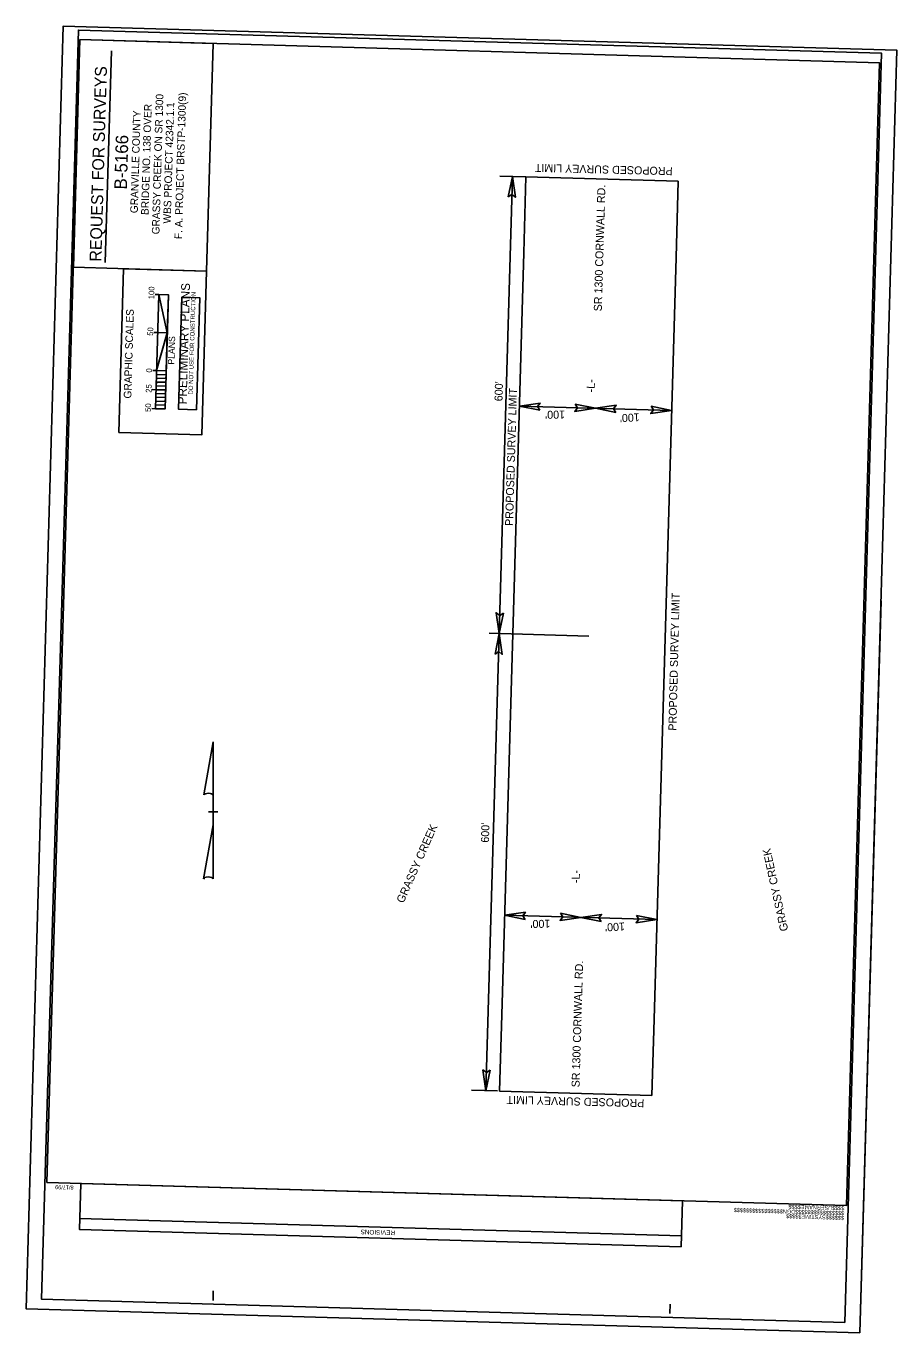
# Model space of a CAD drawing. Extents: x 2098010 to 2099153, y 990167 to 991881.
import ezdxf

# ---------------------------------------------------------------- set-up
doc = ezdxf.new("R2010")
doc.units = 0
for name, color, linetype in [('Default', 7, 'Continuous'), ('Prop Horizontal Alignment', 7, 'Continuous'), ('Prop North Arrow for Plan Sheets CELL', 7, 'Continuous'), ('Prop RDY Alternate Text Blue', 7, 'Continuous'), ('Prop Terminator CELL', 7, 'Continuous'), ('Sheet Block Revision CELL', 7, 'Continuous'), ('Sheet Cutting Line CELL', 7, 'Continuous'), ('Sheet Data Field CELL', 7, 'Continuous'), ('Sheet Plan CELL', 7, 'Continuous'), ('Sheet Plot Border Inside CELL', 7, 'Continuous'), ('Sheet Plot Border Outside CELL', 7, 'Continuous'), ('Sheet Sticker Preliminary CELL', 7, 'Continuous'), ('Sheet Title CELL', 7, 'Continuous')]:
    doc.layers.add(name, color=color, linetype=linetype)

msp = doc.modelspace()

# ---------------------------------------------------------------- linework, layer by layer
at = {"layer": 'Default'}
for p, q in [((2098114, 991571.4), (2098122, 991849)), ((2099104.6, 990167), (2099132.4, 991127.4))]:
    msp.add_line(p, q, dxfattribs=at)
at = {"layer": 'Prop Horizontal Alignment'}
for p, q in [((2098613.8, 990484.7), (2098648.5, 991684.2)), ((2098666.3, 991683.7), (2098632, 991684.6)), ((2098663.4, 991583.8), (2098666.3, 991683.7)), ((2098666.3, 991683.7), (2098866.2, 991678)), ((2098866.2, 991678), (2098863.3, 991578)), ((2098634.5, 990584.2), (2098663.4, 991583.8)), ((2098834.4, 990578.4), (2098863.3, 991578)), ((2098857.5, 991377.1), (2098657.6, 991382.9)), ((2098748.9, 991081), (2098618, 991084.8)), ((2098838.2, 990709.1), (2098638.3, 990714.9)), ((2098634.5, 990584.2), (2098631.6, 990484.2)), ((2098831.5, 990478.5), (2098834.4, 990578.4)), ((2098629.1, 990484.3), (2098594.8, 990485.2)), ((2098631.6, 990484.2), (2098831.5, 990478.5))]:
    msp.add_line(p, q, dxfattribs=at)
for points in [[(2098072.1, 991565), (2098080.7, 991863.8), (2098255.6, 991858.7), (2098246.9, 991559.9)], [(2098131.8, 991348.2), (2098138, 991563.1), (2098246.9, 991559.9), (2098240.7, 991345.1)]]:
    msp.add_lwpolyline(points, close=True, dxfattribs=at)
at = {"layer": 'Prop North Arrow for Plan Sheets CELL'}
for p, q in [((2098243.3, 990872.7), (2098255.6, 990942.2)), ((2098255.7, 990942.2), (2098255.6, 990942.2)), ((2098255.7, 990942.2), (2098255.6, 990942.2)), ((2098255.7, 990942.2), (2098255.7, 990870.5)), ((2098255.7, 990833.3), (2098255.7, 990872.6)), ((2098255.7, 990870.5), (2098255.7, 990872.6)), ((2098249.7, 990850.7), (2098249.6, 990850.7)), ((2098249.7, 990850.7), (2098261.7, 990850.7)), ((2098255, 990850.7), (2098249.7, 990850.7)), ((2098255.7, 990833.3), (2098243.1, 990762.5)), ((2098255.7, 990762.8), (2098255.7, 990833.3))]:
    msp.add_line(p, q, dxfattribs=at)
for centre, start_param, end_param in [((2098249.5, 990872), 0.216388, 2.908219), ((2098249.5, 990762.2), 0.201328, 3.141593)]:
    msp.add_ellipse(centre, major_axis=(6.34, -0.05), ratio=0.461098, start_param=start_param, end_param=end_param, dxfattribs=at)
at = {"layer": 'Prop Terminator CELL'}
for points in [[(2098643.1, 991657.3), (2098648.5, 991684.2), (2098652.5, 991656.9), (2098647.8, 991660.5)], [(2098684.5, 991377.5), (2098657.6, 991382.9), (2098684.9, 991386.9), (2098681.3, 991382.2)], [(2098730.7, 991385.5), (2098757.6, 991380), (2098730.3, 991376), (2098733.9, 991380.7)], [(2098784.4, 991374.6), (2098757.6, 991380), (2098784.8, 991384), (2098781.3, 991379.3)], [(2098830.7, 991382.6), (2098857.5, 991377.1), (2098830.2, 991373.1), (2098833.8, 991377.8)], [(2098636.6, 991111.3), (2098631.2, 991084.4), (2098627.1, 991111.7), (2098631.8, 991108.1)], [(2098625.7, 991057.6), (2098631.2, 991084.4), (2098635.2, 991057.2), (2098630.5, 991060.8)], [(2098665.1, 990709.4), (2098638.3, 990714.9), (2098665.6, 990718.9), (2098662, 990714.2)], [(2098711.4, 990717.4), (2098738.2, 990712), (2098711, 990708), (2098714.5, 990712.7)], [(2098765.1, 990706.5), (2098738.2, 990712), (2098765.5, 990716), (2098761.9, 990711.3)], [(2098811.3, 990714.5), (2098838.2, 990709.1), (2098810.9, 990705.1), (2098814.5, 990709.8)], [(2098619.2, 990511.5), (2098613.8, 990484.7), (2098609.8, 990512), (2098614.5, 990508.4)]]:
    msp.add_lwpolyline(points, close=True, dxfattribs=at)
at = {"layer": 'Sheet Block Revision CELL'}
msp.add_line((2098870.6, 990294.3), (2098080.3, 990317.1), dxfattribs=at)
msp.add_lwpolyline([(2098870.2, 990279.7), (2098079.9, 990302.6), (2098081.7, 990363.1), (2098872, 990340.3)], close=True, dxfattribs=at)
at = {"layer": 'Sheet Cutting Line CELL'}
for p, q in [((2098058.7, 991881.4), (2098010, 990198.6)), ((2099104.6, 990167), (2099153.3, 991849.7)), ((2098010, 990198.6), (2099104.6, 990167))]:
    msp.add_line(p, q, dxfattribs=at)
at = {"layer": 'Sheet Data Field CELL'}
for p, q in [((2098184.3, 991529.4), (2098179.3, 991529.5)), ((2098182.8, 991479.4), (2098177.9, 991479.6)), ((2098180.7, 991404.4), (2098175.7, 991404.6)), ((2098179.9, 991379.5), (2098175, 991379.6))]:
    msp.add_line(p, q, dxfattribs=at)
at = {"layer": 'Sheet Plan CELL'}
for p, q in [((2098037.3, 990364.4), (2098037.3, 990364.4)), ((2099086.9, 990334), (2099086.9, 990334)), ((2098255.5, 990209.5), (2098255.8, 990222)), ((2098855.2, 990192.2), (2098855.6, 990204.7))]:
    msp.add_line(p, q, dxfattribs=at)
msp.add_lwpolyline([(2098080.7, 991863.8), (2098037.3, 990364.4), (2099086.9, 990334), (2099130.3, 991833.4)], close=True, dxfattribs=at)
at = {"layer": 'Sheet Plot Border Inside CELL'}
msp.add_lwpolyline([(2099085, 990180.5), (2099133.1, 991845.8), (2098078.6, 991876.3), (2098030.4, 990211)], close=True, dxfattribs=at)
at = {"layer": 'Sheet Plot Border Outside CELL'}
msp.add_lwpolyline([(2099104.6, 990167), (2099153.3, 991849.7), (2098058.7, 991881.4), (2098010, 990198.6)], close=True, dxfattribs=at)
at = {"layer": 'Sheet Sticker Preliminary CELL'}
msp.add_lwpolyline([(2098233.7, 991378.1), (2098210.2, 991378.8), (2098214.4, 991525.7), (2098237.9, 991525.1)], close=True, dxfattribs=at)
at = {"layer": 'Sheet Title CELL'}
for p, q in [((2098184.3, 991529.4), (2098179.3, 991529.5)), ((2098184.3, 991529.4), (2098180, 991379.4)), ((2098196.8, 991529), (2098184.3, 991529.4)), ((2098192.5, 991379.1), (2098196.8, 991529)), ((2098182.8, 991479.4), (2098177.9, 991479.5)), ((2098182.8, 991479.4), (2098195.3, 991479)), ((2098181.4, 991429.4), (2098176.4, 991429.6)), ((2098180.7, 991404.4), (2098175.7, 991404.6)), ((2098181, 991414.4), (2098193.5, 991414.1)), ((2098180, 991379.4), (2098175, 991379.6)), ((2098175, 991379.6), (2098175, 991379.6)), ((2098180, 991379.4), (2098192.5, 991379.1)), ((2098180, 991379.4), (2098180, 991379.4))]:
    msp.add_line(p, q, dxfattribs=at)
for points in [[(2098184.3, 991529.4), (2098195.3, 991479), (2098196.8, 991529)], [(2098181.4, 991429.4), (2098195.3, 991479), (2098193.9, 991429.1)], [(2098181.1, 991419.4), (2098181.3, 991424.4), (2098193.8, 991424.1), (2098193.6, 991419.1)], [(2098180.5, 991399.4), (2098180.7, 991404.4), (2098193.2, 991404.1), (2098193, 991399.1)], [(2098180.8, 991409.4), (2098181, 991414.4), (2098193.5, 991414.1), (2098193.3, 991409.1)], [(2098180.2, 991389.4), (2098180.4, 991394.4), (2098192.9, 991394.1), (2098192.8, 991389.1)], [(2098180, 991379.4), (2098180.1, 991384.4), (2098192.6, 991384.1), (2098192.5, 991379.1)]]:
    msp.add_lwpolyline(points, close=True, dxfattribs=at)

# ---------------------------------------------------------------- texts
at = {"layer": 'Prop Horizontal Alignment'}
for s, height, rotation, p in [('REQUEST FOR SURVEYS', 15.624, 88.3429, (2098108.8, 991572.2)), ('GRASSY CREEK ON SR 1300', 9.96, 88.3429, (2098185, 991608.1)), ('F. A. PROJECT BRSTP-1300(9)', 9.96, 88.3429, (2098214.7, 991601.9)), ('GRANVILLE COUNTY', 9.96, 88.3429, (2098156.6, 991635.9)), ('BRIDGE NO. 138 OVER ', 9.96, 88.3429, (2098170.8, 991633.5)), ('WBS PROJECT 42342.1.1', 9.96, 88.3429, (2098199.9, 991622.3)), ('B-5166', 16.6, 88.3429, (2098142.3, 991666.9)), ('PROPOSED SURVEY LIMIT', 10.5, 178.5674, (2098859, 991696.3)), ('SR 1300 CORNWALL RD.', 10.5, 88.3429, (2098765.8, 991507.1)), ("600'", 10.5, 88.3429, (2098635.4, 991389.1)), ('PROPOSED SURVEY LIMIT', 10.5, 88.3429, (2098649.3, 991225.5)), ('-L-', 10.5, 88.3429, (2098756.4, 991400.8)), ("100'", 10.5, 180.8331, (2098717.5, 991377.1)), ("100'", 10.5, 183.075, (2098815.3, 991373.6)), ('PROPOSED SURVEY LIMIT', 10.5, 88.5946, (2098863.7, 990956.9)), ("600'", 10.5, 88.3429, (2098617.6, 990810)), ('-L-', 10.5, 88.3429, (2098736.7, 990756.9)), ("100'", 10.5, 180.8331, (2098698.2, 990709)), ("100'", 10.5, 183.075, (2098795.9, 990705.5)), ('SR 1300 CORNWALL RD.', 10.5, 88.3429, (2098736.6, 990489)), ('PROPOSED SURVEY LIMIT', 10.5, 178.5674, (2098821.8, 990473.5))]:
    msp.add_text(s, height=height, rotation=rotation, dxfattribs=at).set_placement(p)
at = {"layer": 'Prop RDY Alternate Text Blue'}
for rotation, p in [(66.1064, (2098505.4, 990729.9)), (102.3437, (2099010.7, 990695.1))]:
    msp.add_text('GRASSY CREEK', height=10.5, rotation=rotation, dxfattribs=at).set_placement(p)
at = {"layer": 'Sheet Block Revision CELL'}
msp.add_text('REVISIONS', height=6, rotation=178.3429, dxfattribs=at).set_placement((2098494.5, 990301.1))
at = {"layer": 'Sheet Data Field CELL'}
for s, p in [('100', (2098178.1, 991523)), ('50', (2098176.7, 991475.1)), ('25', (2098174.6, 991400.3)), ('50', (2098173.8, 991375.2))]:
    msp.add_text(s, height=7.5, rotation=88.3429, dxfattribs=at).set_placement(p)
at = {"layer": 'Sheet Plan CELL'}
for s, p in [('8/17/99', (2098072.4, 990360.1)), ('$$$$$$$$$$$$$$$$DGN$$$$$$$$$$$$$$$$', (2099084.3, 990326.5)), ('$$$$USERNAME$$$$', (2099084.5, 990333)), ('$$$$$$SYSTIME$$$$$', (2099084.1, 990320.4))]:
    msp.add_text(s, height=5.25, rotation=178.3429, dxfattribs=at).set_placement(p)
at = {"layer": 'Sheet Sticker Preliminary CELL'}
for s, height, p in [('PRELIMINARY PLANS', 11.52, (2098220.7, 991385)), ('DO NOT USE FOR CONSTRUCTION', 5.76, (2098228.8, 991397.9))]:
    msp.add_text(s, height=height, rotation=88.3429, dxfattribs=at).set_placement(p)
at = {"layer": 'Sheet Title CELL'}
for s, height, p in [('GRAPHIC SCALES', 10, (2098148.1, 991392.7)), ('PLANS', 8.5, (2098204.7, 991437.2)), ('0', 7.5, (2098175.2, 991426.8))]:
    msp.add_text(s, height=height, rotation=88.3429, dxfattribs=at).set_placement(p)

doc.saveas('drawing.dxf')
